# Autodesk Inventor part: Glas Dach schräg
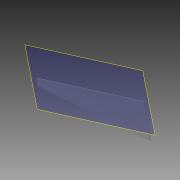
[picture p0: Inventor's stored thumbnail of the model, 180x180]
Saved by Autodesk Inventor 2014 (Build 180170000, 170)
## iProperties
Created: 2013-09
Part Number: Glas Dach schräg
Material: Glas
Document SubType Name: Modeling
Designer: Stefan Tammegger
Mass: 57653.3 g
Surface Area: 42473.5 cm^2
Volume: 26446.5 cm^3
Density: 2.18 g/cm^3
Appearance: Klar
Author: Stefan Tammegger
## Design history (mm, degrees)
workplane "Arbeitsebene1"
sketch "Skizze1"
  geometry: L1 (0, 25)-(-3330, 25) reference; L2 (0, 26.5)-(-3330, 26.5) reference; L3 (0, 35)-(-3330, 35) reference; L4 (0, 33.5)-(-3330, 33.5) reference; L5 (0, 58)-(0, 2) reference; L6 (-3330, 58)-(-3330, 2) reference; L7 (-3327.293, -1017.491)-(0, -196.95) reference; L8 (-3326.934, -1018.947)-(0, -198.495) reference; L9 (-3324.422, -1029.135)-(0, -209.302) reference; L10 (-3324.063, -1030.591)-(0, -210.847) reference; L11 (0, 20)-(-3330, 20); L12 (-3330, 20)-(-3330, -1013.008); L13 (-3330, -1013.008)-(0, -191.8); L14 (0, 20)-(0, -191.8); 1 further point
  constraints: 8 end point, 2 parallel, 2 perpendicular, 2 point on line
  dimensions: "d0" = 5 distance between parallel lines of L1 L11; "d1" = 5 distance between parallel lines of L13 L7
extrude "Extrusion1" new body sketch "Skizze1" distance "d2" = 12.76; taper "d3" = 0 deg
node "Volumenkörper1"
node "Referenz1"
node "Referenz2"
node "Referenz3"
node "Referenz4"
node "Referenz5"
node "Referenz6"
node "Referenz7"
node "Referenz8"
node "Referenz9"
node "Referenz10"
